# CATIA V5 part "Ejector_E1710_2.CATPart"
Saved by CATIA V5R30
Part number: Vyhazovac_2.5x160
Nomenclature: E1710/2.5x160
Description: MEUSBURGER
Property "Material": "1.221"
Publications: "__DrillHole", "Base"
Bounding box of the stored display mesh (mm): x -2.499 to 2.499, y -2.499 to 2.499, z 0 to 152
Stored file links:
  E:\Bakalarka\Model\Forma_v7\Ejector_E1710_2.CATPart
  E:\dev\MoldDesign\intel_a\startup\components\MoldCatalog\Ejector\Meusburger\Ejector_E1710\TableE1710.txt
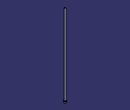
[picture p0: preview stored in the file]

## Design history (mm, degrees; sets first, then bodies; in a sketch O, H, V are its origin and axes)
Parameters
  Ref = "E1710/2.5x160" {design table}
  D1 = 2.5 mm {design table}
  D3 = 5 mm {design table}
  L = 160 mm {design table}
  L3 = 2 mm {design table}
  R = 0.3 mm {design table}
  k_d3 = 6 mm {design table}
  k_d1 = 2.7 mm {design table}
  k_F = 0.3 mm {design table}
  kl = 17 mm {design table}
  Mat = "1.221" {design table}
  HeatTreat = "ISO6751" {design table}
  Offset_Parting = 10 mm
  Anti_Rotation = "Normal"
  Anti_Rotation_D = 1.55 mm
  Anti_Rotation_D_Icut = 1.55 mm
  Add_Length_L = 0.0877 mm
  Add_Length_D3 = 0 mm
  SupplierRef = "Meusburger 2017"
  BmpRef = "F_MldEjectorD1"
  DrillHole_Length = 225 mm
  ValidationTest = false
  Anti_Rotation_D_min = 1.55 mm {= OffSet_D1 /2}
  Anti_Rotation_D_max = 2.425 mm {= D3/2-0.075mm}
  Anti_Rotation_D_ref = 1.55 mm {= Anti_Rotation_D}
  Anti_Rotation_D_Icut_ref = 1.55 mm {= Anti_Rotation_D_Icut}
  Anti_Rotation_Ref_Icut = 2.3246 mm
  Offset_L = 20 mm
  D = 2.5 mm {= D1}
  OffSet_D1 = 3.1 mm {= D1+2*R}
  OffSet_D3 = 6 mm {= D3+1mm}
  XG_Split = -135.5 mm
  YG_Split = 54.5 mm
  ZG_Split = -198 mm
  DirX_Split = 0 mm
  DirY_Split = 0 mm
  DirZ_Split = 1 mm
Set1 "BaseBody"
  Point1 "Base": (0, 0, 0)
  Plane1: type Offset, RefPlane xy-plane, Offset 225 {= DrillHole_Length}, reversed
  Sketch1 "Sketch.2" on xy-plane, origin (0, 0, 0), H (1, 0, 0), V (0, 1, 0)
    point P1 (-0.46, 1.1623)
    point P2 (0.46, 1.1623)
    construction line L1 (-0.46, 1.1623) -> (0.46, 1.1623)
    point P3 (0.46, -1.1623)
    line L2 (0.46, -1.1623) -> (0.46, 1.1623)
    point P4 (-0.46, -1.1623)
    construction line L3 (0.46, -1.1623) -> (-0.46, -1.1623)
    line L4 (-0.46, 1.1623) -> (-0.46, -1.1623)
    point P5 (-0.21, 1.1623)
    arc A1 centre (-0.21, 1.1623) radius 0.25 from (-0.21, 1.4123) to (-0.46, 1.1623) ccw
    point P7 (0.21, 1.1623)
    point P8 (0.21, 1.4123)
    arc A2 centre (0.21, 1.1623) radius 0.25 from (0.46, 1.1623) to (0.21, 1.4123) ccw
    line L5 (-0.21, 1.4123) -> (0.21, 1.4123)
    point P9 (-0.46, -1.1623)
    arc A3 centre (-0.21, -1.1623) radius 0.25 from (-0.46, -1.1623) to (-0.21, -1.4123) ccw
    point P11 (0.21, -1.4123)
    line L6 (-0.21, -1.4123) -> (0.21, -1.4123)
    point P12 (0.46, -1.1623)
    arc A4 centre (0.21, -1.1623) radius 0.25 from (0.21, -1.4123) to (0.46, -1.1623) ccw
    point P14 (-0.46, 1.1623)
    point P15 (-0.46, -1.1623)
    point P16 (0.46, 1.1623)
    point P17 (0.46, -1.1623)
    reference projected circle E1 centre (0, 0) radius 1.25 from edge [face of Shaft1 from Sketch2.L3 | face of Shaft1 from Sketch2.L4]
    reference projected circle E2 centre (0, 0) radius 1.25 from edge [face of Shaft1 from Sketch2.L3 | face of Shaft1 from Sketch2.L4]
    reference projected circle E3 centre (0, 0) radius 1.25 from edge [face of Shaft1 from Sketch2.L3 | face of Shaft1 from Sketch2.L4]
    reference projected circle E4 centre (0, 0) radius 1.25 from edge [face of Shaft1 from Sketch2.L3 | face of Shaft1 from Sketch2.L4]
    point P18 (-0.46, -1.1623)
    point P19 (-0.21, -1.4123)
    point P20 (0.21, -1.4123)
    point P21 (0.46, -1.1623)
    point P22 (-0.21, -1.4123)
    point P23 (0.21, -1.4123)
    distance P14 P15 = 2.3246 (reference)
    distance P16 P17 = 2.3246 (reference)
    distance L1 P14 = 0 (reference)
    radius A1 = 1.25
    distance L4 V = 1.56
    distance L2 V = 2.435
    distance L5 L6 = 5
    horizontal: L1 H, L3 H, L5 H
    vertical: L2 V, L4 V
    coincidence: P5 L1, P7 L1, P3 P12, P14 L4, P15 L4, P16 L2, P17 L2, P14 E1, P15 E2, P16 E3, P17 E4, P3 P21, P4 P18, P20 P23, P19 P22
    tangency: A1 L4, A2 L2, A2 L5, A1 L5
    symmetry: P1 P9 H, A1 A3 H, P8 P11 H, L5 L6 H, P2 P12 H, A2 A4 H
  DatumSurface1
Body1 "PartBody" (main body)
  Sketch2 "Sketch.1" on zx-plane, origin (0, 0, 0), H (-1, 0, 0), V (0, 0, 1)
    point P1 (0, 160)
    line L1 (1.25, 160) -> (0, 160)
    line L2 (1.25, 2) -> (1.25, 160)
    line L3 (2.5, 2) -> (1.25, 2)
    line L4 (2.5, 0) -> (2.5, 2)
    point P5 (0, 0)
    line L5 (0, 0) -> (2.5, 0)
    point P6 (0, 160)
    axis line L6 (0, 160) -> (0, 0)
    point P7 (0, 0)
    point P8 (1.25, 2)
    point P9 (1.25, 2)
    line L7 (0, 160) -> (0, 0)
    distance L5 L3 = 2 {= L3}
    distance L5 L1 = 160 {= L}
    distance L2 L6 = 1.25 {= D1 /2}
    distance L4 L6 = 2.5 {= D3 /2}
    coincidence: L6 P5, P1 L6, L5 H, L6 V, P7 O, P6 P1, P8 P9
    vertical: L2 V, L7 V
    horizontal: L1 H
  Shaft1 "Shaft.1": profile Sketch2, axis Sketch2.L6, angle 360
  Pocket1 "Pocket.1": profile Sketch1, direction (0, 0, 1), length 3, outer side, deactivated
  Pocket2 "Pocket.2": profile Sketch1, direction (0, 0, 1), length 3, outer side, deactivated
  Fillet1: radius 0.3 {= R}, on edge [face of Shaft1 from Sketch2.L2 | face of Shaft1 from Sketch2.L3]
  Pocket3: profile face of Shaft1 from Sketch2.L1, direction along face of Shaft1 from Sketch2.L1 reversed, up to face of DatumSurface1
Body2 "__DrillHole"
  Sketch3 "Sketch.3" on face of Shaft1, origin (0, 0, 0), H (1, 0, 0), V (0, -1, 0)
    point P1 (0, 0)
    reference projected point E1 (0, 0) from Point1
    coincidence: E1 P1
  Hole1 "Hole.1": placed by Sketch3, at (0, 0, 0) direction (0, 0, 1), diameter 3.1 {= OffSet_D1}, depth 140 {= L-Offset_L}
  Sketch4 "Sketch.4" on face of Shaft1, origin (0, 0, 0), H (1, 0, 0), V (0, -1, 0)
    point P1 (0, 0)
    reference projected point E1 (0, 0) from Point1
    coincidence: E1 P1
  Hole2 "Hole.2": placed by Sketch4, at (0, 0, 0) direction (0, 0, 1), diameter 2.5 {= D1}, depth 160 {= L}
  Sketch5 "Sketch.5" on face of Shaft1 from Sketch2.L3, origin (0, 0, 2), H (1, 0, 0), V (0, 1, 0)
    point P1 (0, 0)
    reference projected point E1 (0, 0) from Point1
    coincidence: E1 P1
  Hole3 "Hole.3": placed by Sketch5, at (0, 0, 2) direction (0, 0, -1), diameter 6 {= OffSet_D3}, depth 227 {= L3 +DrillHole_Length}
  Chamfer1: length 0.3 {= k_F}, angle 45, on edge [face of Hole1 | face of Hole3]
  Body3 "__Body.1"
    Pocket4 "Pocket.3": profile Sketch1, direction (0, 0, -1), length 225, opposite side length 2, deactivated
  Assemble1: tool Body3
  Chamfer2: length 0.3 {= k_F}, angle 45, on edge [start face of Pocket4 | face of Hole1], deactivated
  Body4 "__Body.2"
    Pocket5 "Pocket.4": profile Sketch1, direction (0, 0, -1), length 225, opposite side length 2, deactivated
  Assemble2: tool Body4
  Chamfer3: length 0.3 {= k_F}, angle 45, on edge [start face of Pocket5 | face of Hole1], deactivated
Relations
  design table "TableE1710", configuration 134, drives Ref, D1, D3, L, L3, R, k_d3, k_d1, k_F, kl, Mat, HeatTreat
  Offset_L = 20mm (deactivated)
  rule "Cut_Head_rule":
    let sketch_cut (length)
    let PartBody_Pocket_Sketch (Boolean)
    let I_PartBody_Pocket (Boolean)
    let D_PartBody_Pocket (Boolean)
    let N_DrillHole_Hole (Boolean)
    let N_DrillHole_Hole_Sketch (Boolean)
    let I_DrillHole_Pocket (Boolean)
    let D_DrillHole_Pocket (Boolean)
    /* --------------------------------------------------------------------------------------*/
    if Anti_Rotation =="Normal"
    {
    	sketch_cut=Anti_Rotation_D_max
    	PartBody_Pocket_Sketch = false
    	I_PartBody_Pocket = false
    	D_PartBody_Pocket = false
    	N_DrillHole_Hole = true
    	N_DrillHole_Hole_Sketch = true
    	I_DrillHole_Pocket = false
    	D_DrillHole_Pocket = false
    	Chamfer1.Activity= true
    	Chamfer2.Activity= false
    	Chamfer3.Activity= false
    }
    if Anti_Rotation == "I_Cut"
    {
    	sketch_cut=Anti_Rotation_D_Icut_ref
    	PartBody_Pocket_Sketch = true
    	I_PartBody_Pocket = true
    	D_PartBody_Pocket = false
    	N_DrillHole_Hole = false
    	N_DrillHole_Hole_Sketch = false
    	I_DrillHole_Pocket = true
    	D_DrillHole_Pocket = false
    	Chamfer1.Activity= false
    	Chamfer2.Activity= true
    	Chamfer3.Activity= false
    }
    if Anti_Rotation =="D_Cut"
    {
    	sketch_cut=Anti_Rotation_D_max
    	PartBody_Pocket_Sketch = true
    	I_PartBody_Pocket = false
    	D_PartBody_Pocket = true
    	N_DrillHole_Hole = false
    	N_DrillHole_Hole_Sketch = false
    	I_DrillHole_Pocket = false
    	D_DrillHole_Pocket = true
    	Chamfer1.Activity= false
    	Chamfer2.Activity= false
    	Chamfer3.Activity= true
    }
    /* --------------------------------------------------------------------------------------*/
    Sketch1.distance(L2 V) = sketch_cut+0.01mm
    Sketch1.distance(L4 V) =Anti_Rotation_D_ref+0.01mm
    Sketch1.radius(A1) =D/2
    Pocket4.FirstLimit.Depth = DrillHole_Length
    Pocket5.FirstLimit.Depth = DrillHole_Length
    Pocket1.FirstLimit.Depth = L3+1mm
    Pocket2.FirstLimit.Depth = L3+1mm
    Pocket4.SecondLimit.Depth = L3
    Pocket5.SecondLimit.Depth =L3
    Pocket1.Activity = I_PartBody_Pocket
    Pocket2.Activity = D_PartBody_Pocket
    Sketch1.Activity =PartBody_Pocket_Sketch
    Hole3.Activity= N_DrillHole_Hole
    Sketch5.Activity = N_DrillHole_Hole_Sketch
    Pocket4.Activity = I_DrillHole_Pocket
    Pocket5.Activity  = D_DrillHole_Pocket
  rule "Anti_Rotation_Icut_constrain":
    let Ref1(length)
    let Ref2(length)
    let Ref3(length)
    let Diam1(length)
    let Diam2(length)
    let Add_Length_Lmin (length)
    Ref1=Sketch1.distance(P14 P15)
    Ref2=Sketch1.distance(P16 P17)
    Diam1=D
    Diam2=D3
    /* --------------------------------------------------------------------*/
    if Ref1 >Ref2
    	Anti_Rotation_Ref_Icut = Ref1
    else
    	Anti_Rotation_Ref_Icut  =Ref2
    Add_Length_D3 .InferiorRange=Anti_Rotation_Ref_Icut /2+Diam1/2 -Diam2/2
    if Add_Length_D3 .InferiorRange<0mm
    	Add_Length_D3 .InferiorRange=0mm
    if ValidationTest == "true"
    	Ref3   = 2*Add_Length_L +Anti_Rotation_Ref_Icut  +2*Diam1/2
    else
    	Ref3  =Diam2+2*Add_Length_D3
    if Ref3 <Diam2
    {
    	Ref3 =Diam2
    }
    /* --------------------------------------------------------------------*/
    Sketch1.distance(L5 L6) = Ref3
    Add_Length_L .InferiorRange=Diam2/2-Anti_Rotation_Ref_Icut/2-Diam1/2
    Add_Length_Lmin=Diam2/2-Anti_Rotation_Ref_Icut/2-Diam1/2
    if Add_Length_Lmin<0mm
    	Add_Length_L .InferiorRange=0mm
    else
    	Add_Length_L .InferiorRange=Add_Length_Lmin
